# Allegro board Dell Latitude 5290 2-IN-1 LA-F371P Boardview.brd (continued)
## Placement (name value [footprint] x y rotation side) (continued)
D53  ESD8011MUT5G X3DFN2  [ESD101-B1-02ELS_TSSLP-2-4-2]  9.08 37.08 180 top
D54  ESD8011MUT5G X3DFN2  [ESD101-B1-02ELS_TSSLP-2-4-2]  8.95 29.91 0 top
D55  ESD8011MUT5G X3DFN2  [ESD101-B1-02ELS_TSSLP-2-4-2]  8.57 28.83 90 top
D56  ESD8011MUT5G X3DFN2  [ESD101-B1-02ELS_TSSLP-2-4-2]  8.57 28.2 270 top
D57  ESD8011MUT5G X3DFN2  [ESD101-B1-02ELS_TSSLP-2-4-2]  14.03 19.69 90 bottom
D58  ESD8011MUT5G X3DFN2  [ESD101-B1-02ELS_TSSLP-2-4-2]  9.21 22.99 180 top
D59  ESD8011MUT5G X3DFN2  [ESD101-B1-02ELS_TSSLP-2-4-2]  9.21 22.23 180 top
D60  -  [BAT54CW-7-F_SOT323-3]  38.35 22.1 180 top
D61  -  [BAT54CW-7-F_SOT323-3]  18.37 88.83 90 bottom
D62  -  [ESD207-B1-02EL_TSLP-2-19-2]  46.23 79.37 90 bottom
D63  -  [ESD207-B1-02EL_TSLP-2-19-2]  42.93 79.37 90 bottom
D64  -  [ESD207-B1-02EL_TSLP-2-19-2]  42.93 75.81 90 bottom
D65  -  [ESD207-B1-02EL_TSLP-2-19-2]  42.93 77.59 90 bottom
D68  ESD8011MUT5G X3DFN2  [ESD101-B1-02ELS_TSSLP-2-4-2]  18.41 37.59 270 bottom
D69  ESD8011MUT5G X3DFN2  [ESD101-B1-02ELS_TSSLP-2-4-2]  14.1 35.18 90 bottom
D70  ESD8011MUT5G X3DFN2  [ESD101-B1-02ELS_TSSLP-2-4-2]  18.41 38.23 90 bottom
D71  ESD218-B1-02ELS TSSLP-2-4  [ESD3V3S1B-02LS_PG-TSSLP-2-1-2]  9.2 39.14 0 bottom
D72  ESD8011MUT5G X3DFN2  [ESD101-B1-02ELS_TSSLP-2-4-2]  12.7 42.93 270 bottom
D73  ESD8011MUT5G X3DFN2  [ESD101-B1-02ELS_TSSLP-2-4-2]  12.7 41.53 90 bottom
D74  ESD8011MUT5G X3DFN2  [ESD101-B1-02ELS_TSSLP-2-4-2]  12.7 40.52 90 bottom
D75  ESD8011MUT5G X3DFN2  [ESD101-B1-02ELS_TSSLP-2-4-2]  12.7 39.88 270 bottom
D76  ESD8011MUT5G X3DFN2  [ESD101-B1-02ELS_TSSLP-2-4-2]  16.76 42.36 0 bottom
D77  ESD8011MUT5G X3DFN2  [ESD101-B1-02ELS_TSSLP-2-4-2]  8.06 36.64 270 bottom
D78  ESD8011MUT5G X3DFN2  [ESD101-B1-02ELS_TSSLP-2-4-2]  18.16 42.36 180 bottom
D79  ESD8011MUT5G X3DFN2  [ESD101-B1-02ELS_TSSLP-2-4-2]  14.03 18.67 90 bottom
D80  ESD8011MUT5G X3DFN2  [ESD101-B1-02ELS_TSSLP-2-4-2]  18.41 23.37 270 bottom
D81  ESD8011MUT5G X3DFN2  [ESD101-B1-02ELS_TSSLP-2-4-2]  18.41 24.01 90 bottom
D82  ESD218-B1-02ELS TSSLP-2-4  [ESD3V3S1B-02LS_PG-TSSLP-2-1-2]  9.08 24.96 0 bottom
D83  ESD8011MUT5G X3DFN2  [ESD101-B1-02ELS_TSSLP-2-4-2]  12.73 28.78 270 bottom
D84  ESD8011MUT5G X3DFN2  [ESD101-B1-02ELS_TSSLP-2-4-2]  12.73 27.38 90 bottom
D85  ESD8011MUT5G X3DFN2  [ESD101-B1-02ELS_TSSLP-2-4-2]  12.62 24.21 90 bottom
D86  ESD8011MUT5G X3DFN2  [ESD101-B1-02ELS_TSSLP-2-4-2]  12.62 23.57 270 bottom
D87  ESD8011MUT5G X3DFN2  [ESD101-B1-02ELS_TSSLP-2-4-2]  17.14 26.23 90 bottom
D88  ESD8011MUT5G X3DFN2  [ESD101-B1-02ELS_TSSLP-2-4-2]  17.14 27.67 270 bottom
D89  ESD8011MUT5G X3DFN2  [ESD101-B1-02ELS_TSSLP-2-4-2]  8.32 30.55 180 bottom
D91  RB751S40T1G_SOD523-2  [RB520SM-30T2R_EMD2-2]  22.78 93.23 180 bottom
D92  RB751S40T1G_SOD523-2  [RB520SM-30T2R_EMD2-2]  18.38 93.23 0 bottom
D94  RB751S40T1G_SOD523-2  [RB520SM-30T2R_EMD2-2]  30.98 108.69 0 top
D95  RB751S40T1G_SOD523-2  [RB520SM-30T2R_EMD2-2]  30.98 107.47 0 top
D105  RB751S40T1G_SOD523-2  [RB520SM-30T2R_EMD2-2]  21.36 104.52 180 bottom
D106  RB751S40T1G_SOD523-2  [RB520SM-30T2R_EMD2-2]  35.33 101.07 90 bottom
D107  RB751S40T1G_SOD523-2  [RB520SM-30T2R_EMD2-2]  11.66 137 0 bottom
D108  RB751S40T1G_SOD523-2  [RB520SM-30T2R_EMD2-2]  5.87 137.9 0 bottom
D109  RB751S40T1G_SOD523-2  [RB520SM-30T2R_EMD2-2]  55.92 111.25 0 bottom
D110  RB751S40T1G_SOD523-2  [RB520SM-30T2R_EMD2-2]  125.63 175.58 180 top
D111  RB751S40T1G_SOD523-2  [RB520SM-30T2R_EMD2-2]  16.61 108.22 270 bottom
D112  RB751S40T1G_SOD523-2  [RB520SM-30T2R_EMD2-2]  63.11 84.99 90 top
D113  RB751S40T1G_SOD523-2  [RB520SM-30T2R_EMD2-2]  124.02 93.55 270 top
D114  RB751S40T1G_SOD523-2  [RB520SM-30T2R_EMD2-2]  127.02 90.67 180 top
D115  -  [BAT54CW-7-F_SOT323-3]  18.54 83 90 bottom
D116  RB751S40T1G_SOD523-2  [RB520SM-30T2R_EMD2-2]  28.19 98.2 270 bottom
DA1  -  [ESD207-B1-02EL_TSLP-2-19-2]  14.55 162.24 180 bottom
DA3  -  [ESD207-B1-02EL_TSLP-2-19-2]  12.5 162.24 0 bottom
DA4  -  [ESD207-B1-02EL_TSLP-2-19-2]  9.14 162.24 0 bottom
DA5  -  [ESD207-B1-02EL_TSLP-2-19-2]  11.18 162.24 180 bottom
DA6  -  [ESD207-B1-02EL_TSLP-2-19-2]  7.82 162.24 180 bottom
DA8  -  [TVNST52302AB0_SOT523-3]  70.63 16.7 90 bottom
DA9  -  [TVNST52302AB0_SOT523-3]  70.56 13.57 90 bottom
DI1  -  [TVNST52302AB0_SOT523-3]  77.19 23.67 90 bottom
FD1  FIDUCAL  [FIDUCIAL_C40M80]  9.96 165.27 0 top
FD2  FIDUCAL  [FIDUCIAL_C40M80]  76.01 8.32 0 top
FD3  FIDUCIAL  [FIDUCIAL_C40M80]  14.59 171.05 180 bottom
FD4  FIDUCIAL  [FIDUCIAL_C40M80]  76.01 8.32 180 bottom
H1  H_2P3  [H_2P3-G]  110.5 160.15 0 top
H2  H_2P3  [H_2P3-G]  159.4 163.15 0 top
H3  H_2P3  [H_2P3-G]  159.9 109.8 0 top
H4  H_2P3  [H_2P3-G]  118.5 88.8 0 top
H5  -  [H_3P3]  46.2 113.26 0 top
H6  H_2P3  [H_2P3-G]  11.2 90.75 0 top
H7  H_4P0  [H_4P0-G]  5.9 49.3 0 top
H8  H_4P0  [H_4P0-G]  5.9 17.6 0 top
H9  H_2P3  [H_2P3-G]  7.3 177 0 top
H10  -  [H_3P3]  45.79 133.37 0 top
H11  -  [H_3P3]  103.33 134.56 0 top
H12  H_3P6  [H_3P6-G]  82 12.05 0 top
H13  -  [H_3P3]  102.33 110.56 0 top
H14  -  [H_6P0N]  23.63 160.15 0 top
H15  -  [H_6P0N]  28.72 86.5 0 top
H16  -  [H_1P5N]  3.45 146 0 top
H17  -  [H_1P5N]  159.4 159.4 0 top
JANT1  EMI_SPRING  [CLIP_2P8X2P5-S]  67.66 169.6 0 top
JANT2  EMI_SPRING  [CLIP_2P8X2P5-S]  52.15 169.6 0 top
JANT3  BELLW_10093-1021  [BELLW_10093-1021_4P]  38 166.08 90 top
JANT7  EMI_SPRING  [CLIP_2P8X2P5-S]  103.98 169.6 0 top
JAPS1  ACES_50506-01841-P01  [ACES_50506-01841-P01_18P]  28.64 160.85 0 bottom
JCR1  T-SOL_158-1000902614  [T-SOL_158-1000902614_23P-T]  70.14 80.4 180 bottom
JDEG3  ACES_50521-01041-P01  [ACES_50521-01041-P01_10P]  39.21 90.95 180 top
JEDP1  ACES_50398-05071-001  [ACES_50398-05071-001_50P-T]  85.1 20.7 90 top
JESPI1  ACES_50521-01041-P01  [ACES_50521-01041-P01_10P]  55.05 97.31 270 top
JFAN1  ACES_50224-00401-001  [ACES_50224-00401-001_4P]  155.52 134.56 90 top
JIO1  JAE_WP7B-S040VA1-R6000  [JAE_WP7B-S040VA1-R6000_40P-T]  138.05 89.95 180 top
JIO2  ACES_51522-03001-P01  [ACES_51522-03001-P01_30P]  74.55 53.15 90 top
JIR1  ACES_50208-01201-P01  [ACES_50208-01201-P01_12P]  15.1 93.35 90 top
JNGFF1  LOTES_APCI0144-P007A  [LOTES_APCI0144-P007A_75P]  32.88 114.62 180 top
JNGFF2  LOTES_APCI0146-P004A  [LOTES_APCI0146-P004A_75P]  46 82.79 0 top
JNGFF3  LOTES_APCI0145-P004A  [LOTES_APCI0145-P004A_75P]  37.97 52.98 180 top
JP1  SINGA_2SJ3157-001111F  [SINGA_2SJ3157-001111F_6P-T]  6.66 168.55 90 top
JRTC1  ACES_50278-00201-001  [ACES_50278-00201-001_2P]  154.74 99.4 225 bottom
JSIM1  JAE_SF56S006V4A  [JAE_SF56S006V4A_6P-T]  52.04 69.06 180 bottom
JSPI2  ACES_50521-01041-P01  [ACES_50521-01041-P01_10P]  48.65 92.81 90 bottom
JSPK  ACES_50376-00601-001  [ACES_50376-00601-001_6P-T]  81.35 4.8 0 top
JT100  ACES_50278-01201-001  [ACES_50278-01201-001_12P-T]  145.33 89.34 90 top
JUART  CVILU_CI1804M1VRA-NH  [CVILU_CI1804M1VRA-NH_4P]  46.15 123.83 270 bottom
JUFC1  HRS_DF37NC-30DS-0P4V(51)  [HRS_DF37NC-30DS-0P4V-51_30P-T]  121.58 167.59 90 top
JUSB1  TAIWI_USB036-10B7CRL-TW  [TAIWI_USB036-10B7CRL-TW_10P-T]  8.81 106.37 270 top
JUSBC1  JAE_DX07S024XJ2  [JAE_DX07S024XJ2_24P-T]  7.11 43.5 270 top
JUSBC2  JAE_DX07S024XJ2  [JAE_DX07S024XJ2_24P-T]  7.11 28.9 270 top
JWFC1  JAE_WP7B-S034VA1  [JAE_WP7B-S034VA1_34P-T]  121.71 156.94 90 top
JXDP1  JXT_FP270H-061G1AM  [JXT_FP270H-061G1AM_61P]  153.21 118.3 90 bottom
L9  DLW21HN900HQ2L_4P  [MURAT_DLW21HN900HQ2L_4P]  20.3 110.58 90 top
L10  DLW21HN900HQ2L_4P  [MURAT_DLW21HN900HQ2L_4P]  31.67 110.21 90 top
L12  BLM15PX330SN1D_2P  [MURAT_BLM15PX330SN1D_2P]  14.22 159.71 90 bottom
L13  22NH_LQG15HS22NJ02D_5%  [MURAT_LQG15HS22NJ02D_2P]  108.89 169.15 90 top
L14  22NH_LQG15HS22NJ02D_5%  [MURAT_LQG15HS22NJ02D_2P]  109.91 169.15 90 top
L15  BLM15PX330SN1D_2P  [MURAT_BLM15PX330SN1D_2P]  12.83 159.71 90 bottom
L16  BLM15AG121SN1D_L0402_2P  [MURAT_BLM15AG121SN1D_L0402_2P]  111.23 167.07 0 top
L17  BLM15AG121SN1D_L0402_2P  [MURAT_BLM15AG121SN1D_L0402_2P]  111.23 168.21 0 top
L18  BLM15AX700SN1D_2P  [MURAT_BLM15AX100SN1D_2P]  9.27 159.83 180 bottom
L19  BLM15AX700SN1D_2P  [MURAT_BLM15AX100SN1D_2P]  10.8 159.83 0 bottom
L20  BLM15HD601SN1D_2P  [MURAT_BLM15HD182SN1D_2P]  151.64 148.9 270 bottom
L21  BLM15HD601SN1D_2P  [MURAT_BLM15HD182SN1D_2P]  150.37 148.9 270 bottom
L22  1UH_1269AS-H-1R0M-P2_2.5A_20%  [TOKO_1269AS-H-1R0M-P2_2P]  147.19 140.77 270 bottom
L23  BLM18EG221SN1D_2P  [MURAT_BLM18EG221SN1D_2P]  59.22 122.24 0 bottom
L24  HCM1012GH900BP_4P  [INPAQ_HCM1012GH900BP_4P]  25.79 54.35 270 bottom
L30  BLM18EG221SN1D_2P  [MURAT_BLM18EG221SN1D_2P]  59.31 123.42 90 bottom
L31  BLM18SG221TN1D_2P  [MURAT_BLM18SG221TN1D_2P]  22.53 89.38 0 bottom
L32  BLM18SG221TN1D_2P  [MURAT_BLM18SG221TN1D_2P]  22.53 87.94 0 bottom
L80  1.8NH +-0.1NH LQP03TN1N8B02D  [MURAT_LQP03TN1N8B00D_2P]  108.78 165.33 90 top
L81  1.8NH +-0.1NH LQP03TN1N8B02D  [MURAT_LQP03TN1N8B00D_2P]  42.9 166.5 0 top
LA1  BLM21PG600SN1D_2P  [MURAT_BLM21PG600SN1D_2P]  35.43 147.94 270 bottom
LA2  0_0603_5%  [R_0603]  32.32 146.81 90 bottom
LA3  0_0603_5%  [R_0603]  33.53 146.94 270 bottom
LA5  BLM15PX181SN1D_2P  [MURAT_BLM15PX181SN1D_2P]  67.32 17.34 0 bottom
LA6  BLM15PX181SN1D_2P  [MURAT_BLM15PX181SN1D_2P]  67.32 16.26 0 bottom
LA7  BLM15PX181SN1D_2P  [MURAT_BLM15PX181SN1D_2P]  66.43 13.59 0 bottom
LA8  BLM15PX181SN1D_2P  [MURAT_BLM15PX181SN1D_2P]  66.43 12.45 0 bottom
LED4  HT-191UD5_AMBER  [LED_HT-191UD5_2P]  52.31 87.43 270 top
LED5  HT-191UD5_AMBER  [LED_HT-191UD5_2P]  49.05 84.67 180 top
LGA1  -  [LSM6DS3USTR_LGA14_2P5X3]  8.97 143.65 270 bottom
LS1  10NH_LQG15HS10NJ02D_5%_0402  [MURAT_LQG15HS10NJ02D_2P]  116.32 161.58 270 bottom
LT1  HCB2012KF-121T50_2P  [TAI-T_HCB2012KF-121T50_2P]  4.31 33.85 0 top
LT2  HCB2012KF-121T50_2P  [TAI-T_HCB2012KF-121T50_2P]  8.83 32.86 90 top
MC1  680P_0402_50V7K  [C_0402]  79.49 83.61 0 top
MD1  AZ1065-06Q.RDG_MSOP8  [AZ1065-06QPRDG_MSOP8]  21.12 99.65 0 bottom
MIC1  SPK0641HT4H-1-7_8P  [CIRRU_WM7216IMSE-RV_5P]  19.13 173.88 90 top
MIC2  SPK0641HT4H-1-7_8P  [CIRRU_WM7216IMSE-RV_5P]  111.68 174.78 90 top
MIC3  SPK0641HT4H-1-7_8P  [CIRRU_WM7216IMSE-RV_5P]  3.68 125.99 180 top
ML1  CMMI21T-670Y-N_4P  [MURAT_DLW21SN670HQ2L_4P]  24.15 110.59 90 top
ML2  CMMI21T-670Y-N_4P  [MURAT_DLW21SN670HQ2L_4P]  26.18 110.59 90 top
ML3  DLW21HN900HQ2L_4P  [MURAT_DLW21HN900HQ2L_4P]  29.68 104.19 180 top
ML4  CMMI21T-670Y-N_4P  [MURAT_DLW21SN670HQ2L_4P]  21.36 103.02 270 bottom
ML5  CMMI21T-670Y-N_4P  [MURAT_DLW21SN670HQ2L_4P]  23.26 103.02 270 bottom
ML6  DLW21HN900HQ2L_4P  [MURAT_DLW21HN900HQ2L_4P]  25.19 98.96 270 bottom
ML7  HCM1012GH900BP_4P  [INPAQ_HCM1012GH900BP_4P]  33.16 69.3 0 bottom
ML8  HCM1012GH900BP_4P  [INPAQ_HCM1012GH900BP_4P]  36.97 54.28 270 bottom
ML9  MCM1012B900F06BP_4P  [INPAQ_MCM1012B900F06BP_4P]  14.98 42.48 180 bottom
ML10  MCM1012B900F06BP_4P  [INPAQ_MCM1012B900F06BP_4P]  14.98 40.45 180 bottom
ML11  MCM1012B900F06BP_4P  [INPAQ_MCM1012B900F06BP_4P]  15 28.33 180 bottom
ML12  MCM1012B900F06BP_4P  [INPAQ_MCM1012B900F06BP_4P]  15.41 24.14 180 bottom
ML14  HCM1012GH900BP_4P  [INPAQ_HCM1012GH900BP_4P]  50.17 17.34 0 bottom
NOREF  -  []  50.8 39.16 0 top
NOREF#2  -  []  50.77 52.53 0 top
NOREF#3  -  []  52.29 17.34 0 top
NOREF#4  -  []  103.33 134.56 0 top
NOREF#5  -  []  46.2 113.26 0 top
NOREF#6  -  []  48.82 38.62 0 top
NOREF#7  -  []  110.5 160.15 0 top
NOREF#8  -  []  61.35 27.6 0 top
NOREF#9  -  []  82 12.05 0 top
NOREF#10  -  []  109.31 32.44 0 top
NOREF#11  -  []  159.9 109.8 0 top
NOREF#12  -  []  110.5 160.15 0 top
NOREF#13  -  []  118.5 88.8 0 top
NOREF#14  -  []  97.41 74.74 0 top
NOREF#15  -  []  28.83 72.71 0 top
NOREF#16  -  []  11.2 90.75 0 top
NOREF#17  -  []  69.43 33.46 0 top
NOREF#18  -  []  0 178.5 0 top
NOREF#19  -  []  75.2 22.38 270 top
NOREF#20  -  []  7.3 177 0 top
NOREF#21  -  []  159.4 163.15 0 top
NOREF#22  -  []  102.33 110.56 0 top
NOREF#23  -  []  43.05 64.66 0 top
NOREF#24  -  []  45.79 133.37 0 top
NOREF#25  -  []  76.21 50.34 180 bottom
NOREF#26  -  []  84.78 45.38 180 bottom
PC100  2200P_0402_50V7K  [C_0402]  13.63 41.86 90 top
PC101  0.1U_0402_25V6  [C_0402]  12.69 41.86 90 top
PC102  100P_0201_25V7K  [C_0201]  13.49 38.04 270 top
PC103  0.01U_0402_25V7K  [C_0402]  12.75 37.96 270 top
PC104  1000P_0201_50V7K  [C_0201]  19.91 40.74 90 top
PC105  100P_0201_25V7K  [C_0201]  19.25 40.74 90 top
PC106  0.1U_0402_25V6  [C_0402]  14.63 41.85 90 top
PC107  1U_0603_25V6K  [C_0603]  18.06 40.88 90 top
PC108  2200P_0402_50V7K  [C_0402]  15.6 41.85 90 top
PC109  0.47U_0402_25V6K  [C_0402]  15.42 37.96 270 top
PC110  680P_0402_50V7K  [C_0402]  36.7 32.45 90 top
PC111  680P_0402_50V7K  [C_0402]  27.79 36.72 90 top
PC112  680P_0402_50V7K  [C_0402]  29.72 33.72 180 top
PC114  100P_0201_25V7K  [C_0201]  12.67 25.67 270 top
PC115  1U_0603_25V6K  [C_0603]  16.48 29.35 90 top
PC116  0.1U_0402_25V6  [C_0402]  13.28 30.29 0 top
PC117  2200P_0402_50V7K  [C_0402]  17.55 28.27 90 top
PC118  100P_0201_25V7K  [C_0201]  21.01 28.3 90 top
PC119  1000P_0201_50V7K  [C_0201]  20.38 28.3 90 top
PC120  2200P_0402_50V7K  [C_0402]  13.28 29.4 0 top
PC121  0.1U_0402_25V6  [C_0402]  18.54 28.26 90 top
PC122  0.01U_0402_25V7K  [C_0402]  13.46 25.59 270 top
PC123  0.47U_0402_25V6K  [C_0402]  14.35 25.59 270 top
PC124  680P_0402_50V7K  [C_0402]  24.51 24.4 270 top
PC125  0.01U_0201_16V7  [C_0201]  23.27 43.97 90 top
PC126  1000P_0402_50V7K  [C_0402]  140.21 106.95 270 top
PC127  0.01U_0402_25V7K  [C_0402]  139.83 111.11 90 bottom
PC128  1U_0603_25V6K  [C_0603]  14.61 48.58 180 top
PC129  1U_0402_16V6K  [C_0402]  22.06 48.78 270 top
PC130  0.1U_0201_10V6K  [C_0201]  27.3 43.41 270 top
PC131  1U_0402_16V6K  [C_0402]  20.19 48.68 0 bottom
PC132  2200P_0402_50V7K  [C_0402]  139.06 106.03 90 top
PC133  10U_0603_25V6M  [C_0603]  16.78 40.88 90 top
PC134  10U_0603_25V6M  [C_0603]  15.21 29.35 90 top
PC140  1000P_0402_50V7K  [C_0402]  143.03 127.46 180 top
PC144  100P_0402_50V8J  [C_0402]  28.57 48.83 90 bottom
PC145  0.1U_0402_10V7K  [C_0402]  30.73 49.34 90 bottom
PC146  2.2U_0402_25V6M  [C_0402]  31.88 47.36 90 bottom
PC147  0.1U_0402_10V7K  [C_0402]  39.57 47.68 180 top
PC148  100P_0402_50V8J  [C_0402]  37.22 38.93 180 top
PC149  2.2U_0402_25V6M  [C_0402]  39.55 44.79 90 top
PC150  0.01U_0402_50V7K  [C_0402]  30.3 48.07 270 top
PC151  0.01U_0402_50V7K  [C_0402]  35.45 40.71 180 top
PC280  4.7U_0402_6.3V6M  [C_0402]  144.78 118.7 270 top
PC281  10U_0402_6.3V6M  [C_0402]  30.1 46.24 270 bottom
PC282  10U_0402_6.3V6M  [C_0402]  38.02 43.94 0 top
PC283  0.1U_0402_10V7K  [C_0402]  31.88 22.16 0 top
PC284  100P_0402_50V8J  [C_0402]  35.81 21.27 0 top
PC285  10U_0402_6.3V6M  [C_0402]  35.81 18.99 270 top
PC286  0.01U_0402_50V7K  [C_0402]  30.73 18.48 270 top
PC301  0.1U_0402_25V6  [C_0402]  120.64 97.92 0 top
PC302  10U_0603_25V6M  [C_0603]  128.91 98.74 0 top
PC303  0.1U_0402_25V6  [C_0402]  127.76 98.62 270 top
PC304  10U_0603_25V6M  [C_0603]  129.54 98.93 270 bottom
PC305  10U_0603_25V6M  [C_0603]  124.46 101.35 90 bottom
PC306  2200P_0402_50V7K  [C_0402]  127.13 98.82 270 bottom
PC307  10U_0603_25V6M  [C_0603]  124.59 97.86 180 top
PC308  10U_0603_25V6M  [C_0603]  123.19 101.35 90 top
PC309  10U_0603_25V6M  [C_0603]  124.46 101.35 90 top
PC310  10U_0603_25V6M  [C_0603]  128.27 98.93 270 bottom
PC312  4.7U_0603_25V6K  [C_0603]  131.19 128.4 270 bottom
PC313  1U_0402_25V6K  [C_0402]  132.77 127.83 0 top
PC314  1U_0402_25V6K  [C_0402]  132.77 126.94 0 top
PC315  10U_0603_25V6M  [C_0603]  143 121.54 90 bottom
PC316  10U_0603_25V6M  [C_0603]  144.27 121.54 90 top
PC317  10U_0603_25V6M  [C_0603]  143 121.54 90 top
PC318  10U_0603_25V6M  [C_0603]  140.46 121.54 90 top
PC319  10U_0603_25V6M  [C_0603]  140.46 121.54 90 bottom
PC320  10U_0603_25V6M  [C_0603]  139.19 121.54 90 top
PC321  0.1U_0402_25V6  [C_0402]  145.41 121.78 90 top
PC322  10U_0603_25V6M  [C_0603]  143.07 116.71 0 bottom
PC323  10U_0603_25V6M  [C_0603]  143.07 116.71 0 top
PC324  10U_0603_25V6M  [C_0603]  144.27 121.54 90 bottom
PC325  10U_0603_25V6M  [C_0603]  141.73 121.54 90 top
PC326  10U_0603_25V6M  [C_0603]  141.73 121.54 90 bottom
PC327  1U_0402_25V6K  [C_0402]  80.58 158.87 90 top
PC328  1U_0402_25V6K  [C_0402]  63.69 158.93 90 top
PC329  2200P_0402_50V7K  [C_0402]  145.41 121.78 90 bottom
PC330  0.22U_0603_25V7K  [C_0603]  129.73 124.65 0 bottom
PC331  0.1U_0402_25V6  [C_0402]  134.71 130.81 90 bottom
PC332  1U_0603_25V6K  [C_0603]  130.75 129.48 180 bottom
PC333  1U_0603_25V6K  [C_0603]  131.83 132.34 270 bottom
PC334  1U_0402_6.3V6K  [C_0402]  132.77 128.72 0 top
PC335  1U_0402_6.3V6K  [C_0402]  134.54 128.46 0 top
PC336  0.22U_0603_25V7K  [C_0603]  135 122.56 270 bottom
PC337  1U_0402_25V6K  [C_0402]  93.28 156.14 90 top
PC338  1U_0402_25V6K  [C_0402]  53.85 155.37 90 top
PC339  4700P_0402_25V7K  [C_0402]  138.63 117.54 180 top
PC340  2200P_0402_50V7K  [C_0402]  137.41 114.61 90 top
PC341  0.1U_0402_25V6  [C_0402]  135.13 123.94 90 top
PC342  680P_0402_50V7K  [C_0402]  134.37 100.47 270 bottom
PC343  680P_0402_50V7K  [C_0402]  127.51 120.64 90 bottom
PC345  1U_0402_25V6K  [C_0402]  136.21 120.89 90 bottom
PC346  4.7U_0603_25V6K  [C_0603]  136.84 122.87 0 bottom
PC347  1U_0402_25V6K  [C_0402]  138.87 121.81 270 bottom
PC348  560P_0402_50V7K  [C_0402]  139.24 127.7 0 bottom
PC349  0.01U_0402_16V7K  [C_0402]  140.14 125.85 90 bottom
PC350  0.1U_0402_25V6  [C_0402]  32.01 121.56 270 bottom
PC351  0.1U_0402_25V6  [C_0402]  139.24 125.41 0 top
PC352  0.1U_0402_25V6  [C_0402]  154.72 125.49 90 top
PC400  0.1U_0603_50V7K  [C_0603]  77.85 73.79 270 top
PC401  1U_0805_50V7K  [C_0805]  77.85 74.91 90 top
PC402  0.1U_0402_25V6  [C_0402]  77.71 81.83 0 top
PC403  2.2U_0603_50V6K  [C_0603]  70.68 67.25 180 top
PC404  2.2U_0603_50V6K  [C_0603]  70.68 68.52 180 top
PC405  2.2U_0603_50V6K  [C_0603]  71.69 71.06 0 top
PC406  0.1U_0603_50V7K  [C_0603]  71.69 69.79 0 top
PC407  220P_0402_50V7K  [C_0402]  69.28 76 90 top
PC408  470P_0402_50V7K  [C_0402]  76.71 85.92 180 top
PC409  470P_0402_50V7K  [C_0402]  76.71 84.06 90 top
PC410  470P_0402_50V7K  [C_0402]  75.82 84.06 90 top
PC411  100P_0402_50V8J  [C_0402]  69.39 86.17 0 top
PC412  470P_0402_50V7K  [C_0402]  74.93 84.06 90 top
PC413  470P_0402_50V7K  [C_0402]  74.04 84.06 90 top
PC414  470P_0402_50V7K  [C_0402]  73.15 84.06 90 top
PC415  470P_0402_50V7K  [C_0402]  72.21 84.14 180 top
PC416  100P_0402_50V8J  [C_0402]  79.45 78.82 270 top
PC417  470P_0402_50V7K  [C_0402]  70.31 82.62 180 top
PC418  2.2U_0603_50V6K  [C_0603]  71.64 68.52 0 top
PC500  0.22U_0402_16V7K  [C_0402]  123.27 114.11 180 top
PC501  0.1U_0402_25V6  [C_0402]  119.84 120.33 180 top
PC502  2200P_0402_50V7K  [C_0402]  119.84 120.33 180 bottom
PC503  10U_0603_25V6M  [C_0603]  120.08 121.48 180 bottom
PC504  10U_0603_25V6M  [C_0603]  120.08 121.48 180 top
PC505  4.7U_0402_6.3V6M  [C_0402]  116.4 118.25 270 top
PC506  22U_0603_6.3V6M  [C_0603]  118.05 107 180 top
PC507  22U_0603_6.3V6M  [C_0603]  118.05 107 180 bottom
PC508  22U_0603_6.3V6M  [C_0603]  120.33 107 0 bottom
PC509  22U_0603_6.3V6M  [C_0603]  120.33 107 0 top
PC510  1U_0402_16V6K  [C_0402]  122.43 116.26 90 top
PC511  680P_0603_50V7K  [C_0603]  119.7 117.79 180 bottom
PC513  0.22U_0402_16V7K  [C_0402]  41.71 156.53 0 top
PC514  0.47U_0402_25V6K  [C_0402]  45.26 152.59 0 bottom
PC515  0.047U_0402_25V7K  [C_0402]  45.26 153.48 0 bottom
PC516  10U_0603_25V6M  [C_0603]  45.59 151.47 0 top
PC517  10U_0603_25V6M  [C_0603]  45.59 151.32 0 bottom
PC518  4.7U_0402_6.3V6M  [C_0402]  48.9 156.1 270 top
PC519  22U_0603_6.3V6M  [C_0603]  48.45 162.37 0 top
PC520  22U_0603_6.3V6M  [C_0603]  48.45 161.1 0 bottom
PC521  22U_0603_6.3V6M  [C_0603]  48.45 162.37 0 bottom
PC522  22U_0603_6.3V6M  [C_0603]  48.45 161.1 0 top
PC523  1U_0402_16V6K  [C_0402]  42.67 154.32 270 top
PC524  680P_0603_50V7K  [C_0603]  48.32 156.15 0 bottom
PC526  0.22U_0402_16V7K  [C_0402]  123.52 140.45 180 top
PC527  0.1U_0402_25V6  [C_0402]  120.35 147.18 180 top
PC528  2200P_0402_50V7K  [C_0402]  120.35 147.18 180 bottom
PC529  10U_0603_25V6M  [C_0603]  120.33 148.32 180 bottom
PC530  10U_0603_25V6M  [C_0603]  120.33 148.32 180 top
PC531  4.7U_0402_6.3V6M  [C_0402]  116.59 143.04 90 top
PC532  22U_0603_6.3V6M  [C_0603]  116.59 144.9 90 top
PC533  22U_0603_6.3V6M  [C_0603]  122.62 138.29 0 bottom
PC534  22U_0603_6.3V6M  [C_0603]  122.62 137.02 0 bottom
PC535  22U_0603_6.3V6M  [C_0603]  122.62 137.02 0 top
PC536  1U_0402_16V6K  [C_0402]  123 142.66 90 top
PC537  680P_0603_50V7K  [C_0603]  118.36 144.45 90 bottom
PC600  0.22U_0402_16V7K  [C_0402]  112.09 116.02 180 top
PC601  680P_0402_50V7K  [C_0402]  105.87 120.46 180 bottom
PC602  220P_0402_50V8J  [C_0402]  111.84 118.3 180 top
PC603  22U_0603_6.3V6M  [C_0603]  108.78 106.24 180 top
PC604  22U_0603_6.3V6M  [C_0603]  108.78 107.51 180 top
PC605  22U_0603_6.3V6M  [C_0603]  110.17 106.24 0 top
PC606  22U_0603_6.3V6M  [C_0603]  110.17 107.51 0 top
PC607  10U_0603_25V6M  [C_0603]  107.77 124.54 180 top
PC608  0.1U_0402_25V6  [C_0402]  108 123.18 180 top
PC609  2200P_0402_25V7K  [C_0402]  108 122.3 180 top
PC610  10U_0402_6.3V6M  [C_0402]  104.47 119.45 180 top
PC611  10U_0402_6.3V6M  [C_0402]  104.47 118.49 180 top
PC612  0.22U_0402_10V6K  [C_0402]  104.47 119.45 180 bottom
PC613  0.1U_0402_10V7K  [C_0402]  107.31 122.42 90 bottom
PC614  1U_0402_16V6K  [C_0402]  104.47 120.72 180 top
PC615  0.1U_0402_10V7K  [C_0402]  110.92 121.86 0 top
PC700  0.22U_0402_10V6K  [C_0402]  131.95 138.57 270 top
PC701  680P_0402_50V7K  [C_0402]  128.91 144.54 270 bottom
PC702  0.1U_0603_25V7K  [C_0603]  124.9 144.65 0 top
PC703  2200P_0402_50V7K  [C_0402]  125.74 141.23 180 top
PC704  0.1U_0402_25V6  [C_0402]  125.68 141.23 180 bottom
PC705  10U_0603_25V6M  [C_0603]  125.35 140.07 270 bottom
PC706  10U_0603_25V6M  [C_0603]  125.35 140.07 270 top
PC707  330P_0402_50V7K  [C_0402]  132.79 140.84 180 bottom
PC708  22U_0603_6.3V6M  [C_0603]  131.76 146.5 0 top
PC709  22U_0603_6.3V6M  [C_0603]  131.76 146.5 0 bottom
PC710  22U_0603_6.3V6M  [C_0603]  131.76 147.77 0 bottom
PC711  22U_0603_6.3V6M  [C_0603]  131.76 147.77 0 top
PC712  2.2U_0402_6.3V6M  [C_0402]  131.81 143.38 0 top
PC713  4.7U_0603_6.3V6K  [C_0603]  131.76 142.31 0 top
PC720  0.1U_0402_25V6  [C_0402]  142.82 140.91 180 top
PC721  22P_0402_50V8J  [C_0402]  135.05 143.32 0 top
PC722  22U_0603_6.3V6M  [C_0603]  135.95 144.97 180 top
PC723  0.1U_0402_25V6  [C_0402]  140.11 138.42 270 top
PC724  2200P_0402_50V7K  [C_0402]  139.22 138.42 270 top
PC725  10U_0603_25V6M  [C_0603]  141.15 138.41 270 top
PC726  3300P_0402_50V7-K  [C_0402]  138.33 138.43 270 top
PC727  680P_0402_50V7K  [C_0402]  137.6 143.14 270 bottom
PC728  0.1U_0402_25V6  [C_0402]  104.44 96.59 0 top
PC729  22P_0402_50V8J  [C_0402]  112.2 95.45 270 top
PC730  22U_0603_6.3V6M  [C_0603]  108.53 89.9 270 top
PC731  0.1U_0402_25V6  [C_0402]  107.57 99.43 90 top
PC732  2200P_0402_50V7K  [C_0402]  108.46 99.43 90 top
PC733  10U_0603_25V6M  [C_0603]  109.6 99.44 90 top
PC734  3300P_0402_50V7-K  [C_0402]  111.3 98.11 0 top
PC735  680P_0402_50V7K  [C_0402]  105.54 92.32 90 top
PC736  22U_0603_6.3V6M  [C_0603]  109.82 89.9 270 top
PC800  0.1U_0402_25V6  [C_0402]  124.08 130.8 90 top
PC801  10U_0603_25V6M  [C_0603]  126.81 128.21 0 top
PC802  10U_0603_25V6M  [C_0603]  126.81 128.21 0 bottom
PC803  22U_0603_6.3V6M  [C_0603]  119.44 129.8 0 top
PC804  22U_0603_6.3V6M  [C_0603]  119.44 132.4 0 top
PC805  22U_0603_6.3V6M  [C_0603]  119.43 131.09 0 top
PC806  0.1U_0402_25V6  [C_0402]  126.8 127.07 0 top
PC807  2200P_0402_50V7K  [C_0402]  126.8 127.07 0 bottom
PC808  680P_0402_50V7K  [C_0402]  122.36 127.24 90 bottom
PC809  100P_0402_50V8J  [C_0402]  123.83 124.6 270 top
PC810  0.1U_0402_25V6  [C_0402]  50.28 147.77 0 top
PC811  10U_0603_25V6M  [C_0603]  52.64 146.5 0 top
PC812  10U_0603_25V6M  [C_0603]  52.64 146.5 0 bottom
PC813  22U_0603_6.3V6M  [C_0603]  45.97 147.13 90 bottom
PC814  22U_0603_6.3V6M  [C_0603]  45.97 147.13 90 top
PC815  22U_0603_6.3V6M  [C_0603]  44.77 147.13 90 top
PC816  0.1U_0402_25V6  [C_0402]  52.63 145.35 0 bottom
PC817  2200P_0402_50V7K  [C_0402]  52.63 145.35 0 top
PC818  680P_0402_50V7K  [C_0402]  49.28 147.08 270 bottom
PC819  470P_0402_50V7K  [C_0402]  50.16 141.75 270 top
PC900  0.1U_0402_25V6  [C_0402]  54.76 150.97 0 bottom
PC901  1U_0603_10V6K  [C_0603]  63.09 149.65 0 bottom
PC902  4.7U_0603_10V6K  [C_0603]  55.88 153.9 180 bottom
PC903  0.1U_0402_25V6  [C_0402]  63.42 145.16 270 bottom
PC904  220P_0402_50V8J  [C_0402]  68.1 155.79 180 bottom
PC905  470P_0402_50V7K  [C_0402]  66.32 153.76 180 bottom
PC906  33P_0402_50V8J  [C_0402]  66.32 152.87 180 bottom
PC907  1U_0603_10V6K  [C_0603]  55.04 155.96 180 bottom
PC911  0.01U_0402_50V7K  [C_0402]  55.95 159.39 270 bottom
PC931  0.01U_0402_16V7K  [C_0402]  58.55 160.24 180 bottom
PC932  0.01U_0402_16V7K  [C_0402]  66.42 159.83 0 bottom
PC933  0.01U_0402_16V7K  [C_0402]  68.98 155.87 270 bottom
PC1003  47U_D3_20VM_R45M  [C_PSKV151D476M045C]  76.66 161.05 270 top
PC1007  1000P_0402_50V7K  [C_0402]  82 162.99 90 top
PC1008  1000P_0402_50V7K  [C_0402]  97.94 159.78 0 top
PC1009  1U_0603_25V6K  [C_0603]  82.42 156.85 180 top
PC1010  10U_0603_25V6M  [C_0603]  66.61 162.63 0 top
PC1011  1000P_0402_50V7K  [C_0402]  65.15 163.01 90 top
PC1012  1000P_0402_50V7K  [C_0402]  53.85 158.64 270 top
PC1013  1U_0603_25V6K  [C_0603]  94.77 154.23 270 top
PC1014  1U_0603_25V6K  [C_0603]  55.66 153.35 180 top
PC1028  47U_D3_20VM_R45M  [C_PSKV151D476M045C]  94.64 161.79 180 top
PC1030  47U_D3_20VM_R45M  [C_PSKV151D476M045C]  57.96 161.46 180 top
PC1103  100P_0603_50V7  [C_0603]  83.31 161.42 0 bottom
PC1104  10U_0603_25V6M  [C_0603]  83.31 162.63 0 bottom
PC1105  10U_0603_25V6M  [C_0603]  83.31 162.63 0 top
PC1106  0.1U_0402_25V6  [C_0402]  81.1 162.98 90 top
PC1107  100P_0603_50V7  [C_0603]  69.15 161.37 90 bottom
PC1108  680P_0603_50V7K  [C_0603]  91.3 158.84 180 top
PC1109  10U_0603_25V6M  [C_0603]  66.61 162.63 0 bottom
PC1110  0.22U_0603_25V7K  [C_0603]  79.88 157.93 270 top
PC1111  680P_0603_50V7K  [C_0603]  71.17 159.72 270 top
PC1112  0.1U_0402_25V6  [C_0402]  64.27 163.01 90 top
PC1113  1U_0603_25V6K  [C_0603]  65.53 156.85 180 top
PC1114  0.22U_0603_25V7K  [C_0603]  63.04 157.79 270 top
PC1115  100P_0603_50V7  [C_0603]  97.57 157.61 0 bottom
PC1116  10U_0603_25V6M  [C_0603]  97.57 158.82 0 bottom
PC1117  680P_0603_50V7K  [C_0603]  102.93 157.18 180 top
PC1118  0.1U_0402_25V6  [C_0402]  98.02 161.89 0 top
PC1119  10U_0603_25V6M  [C_0603]  97.98 160.82 0 top
PC1120  0.22U_0603_25V7K  [C_0603]  93.09 155.04 270 top
PC1121  10U_0603_25V6M  [C_0603]  59.44 158.62 270 top
PC1122  10U_0603_25V6M  [C_0603]  60.64 158.62 270 top
PC1123  0.1U_0402_25V6  [C_0402]  52.96 158.64 270 top
PC1124  680P_0603_50V7K  [C_0603]  54.76 149.37 270 top
PC1125  43P_0603_50V8  [C_0603]  51.88 158.56 270 top
PC1126  0.22U_0603_25V7K  [C_0603]  53.1 154.47 270 top
PC1200  220U_B2_2.5VM_R15M  [C_B2]  75.64 145.96 270 top
PC1201  220U_B2_2.5VM_R15M  [C_B2]  91.23 142.46 180 top
PC1202  220U_B2_2.5VM_R15M  [C_B2]  78.84 145.96 270 top
PC1203  220U_B2_2.5VM_R15M  [C_B2]  92.51 145.65 270 top
PC1207  220U_B2_2.5VM_R15M  [C_B2]  100.97 142.48 0 top
PC1208  220U_B2_2.5VM_R15M  [C_B2]  108.91 141.75 180 top
PC1209  220U_B2_2.5VM_R15M  [C_B2]  108.91 145.11 180 top
PC1210  10U_0402_6.3V6M  [C_0402]  92.08 123.18 90 bottom
PC1211  10U_0402_6.3V6M  [C_0402]  92.96 123.18 90 bottom
PC1212  10U_0402_6.3V6M  [C_0402]  89.98 126.51 270 bottom
PC1213  10U_0402_6.3V6M  [C_0402]  89.03 129.86 90 bottom
PC1214  10U_0402_6.3V6M  [C_0402]  84.66 132.53 180 bottom
PC1215  10U_0402_6.3V6M  [C_0402]  84.66 131.64 180 bottom
PC1216  10U_0402_6.3V6M  [C_0402]  84.66 130.75 180 bottom
PC1217  220U_B2_2.5VM_R15M  [C_B2]  57.76 142.18 0 top
PC1218  10U_0402_6.3V6M  [C_0402]  91.69 128.77 90 bottom
PC1220  47U_0603_6.3V6M  [C_0603]  73.47 127.45 0 bottom
PC1221  10U_0402_6.3V6M  [C_0402]  73.55 131.7 180 bottom
PC1222  47U_0603_6.3V6M  [C_0603]  73.47 126.24 0 bottom
PC1223  47U_0805_6.3V6M  [C_0805]  78.21 137.67 0 bottom
PC1224  47U_0805_6.3V6M  [C_0805]  78.21 135.96 0 bottom
PC1225  10U_0402_6.3V6M  [C_0402]  78.16 131.7 0 bottom
PC1227  47U_0805_6.3V6M  [C_0805]  78.21 134.24 0 bottom
PC1228  47U_0805_6.3V6M  [C_0805]  74.51 137.67 180 bottom
PC1229  10U_0402_6.3V6M  [C_0402]  72.91 129.03 180 bottom
PC1230  47U_0805_6.3V6M  [C_0805]  77.62 124.78 180 bottom
PC1231  47U_0805_6.3V6M  [C_0805]  73.06 124.78 0 bottom
PC1232  47U_0805_6.3V6M  [C_0805]  74.51 135.96 180 bottom
PC1233  47U_0603_6.3V6M  [C_0603]  73.47 122.11 0 bottom
PC1234  47U_0603_6.3V6M  [C_0603]  77.85 132.78 0 bottom
PC1237  47U_0603_6.3V6M  [C_0603]  74.1 132.78 180 bottom
PC1246  47U_0603_6.3V6M  [C_0603]  77.22 123.32 180 bottom
PC1247  47U_0603_6.3V6M  [C_0603]  73.47 123.32 0 bottom
PC1248  47U_0805_6.3V6M  [C_0805]  74.51 134.24 180 bottom
PC1250  10U_0402_6.3V6M  [C_0402]  76.97 121.03 180 bottom
PC1251  47U_0603_6.3V6M  [C_0603]  77.22 122.11 180 bottom
PC1252  47U_0603_6.3V6M  [C_0603]  77.22 127.45 180 bottom
PC1253  47U_0603_6.3V6M  [C_0603]  103.38 129.29 270 top
PC1254  47U_0603_6.3V6M  [C_0603]  99.76 125.29 90 top
PC1255  47U_0603_6.3V6M  [C_0603]  102.17 129.29 270 top
PC1256  47U_0603_6.3V6M  [C_0603]  77.22 126.24 180 bottom
PC1258  47U_0603_6.3V6M  [C_0603]  100.97 129.29 270 bottom
PC1259  1U_0201_6.3V6M  [C_0201]  72.77 118.98 270 bottom
PC1260  1U_0201_6.3V6M  [C_0201]  78.26 130.94 0 bottom
PC1261  1U_0201_6.3V6M  [C_0201]  78.26 130.37 0 bottom
PC1262  1U_0201_6.3V6M  [C_0201]  78.26 129.22 0 bottom
PC1263  1U_0201_6.3V6M  [C_0201]  78.26 128.65 0 bottom
PC1265  1U_0201_6.3V6M  [C_0201]  78.26 129.8 0 bottom
PC1266  1U_0201_6.3V6M  [C_0201]  75.06 118.98 270 bottom
PC1267  1U_0201_6.3V6M  [C_0201]  75.63 118.98 270 bottom
PC1268  1U_0201_6.3V6M  [C_0201]  76.2 118.98 270 bottom
PC1269  1U_0201_6.3V6M  [C_0201]  74.76 121.22 0 bottom
PC1270  1U_0201_6.3V6M  [C_0201]  74.76 120.65 0 bottom
PC1272  1U_0201_6.3V6M  [C_0201]  74.47 118.96 270 bottom
PC1273  1U_0201_6.3V6M  [C_0201]  73.9 118.96 270 bottom
PC1274  1U_0201_6.3V6M  [C_0201]  73.33 118.96 270 bottom
PC1275  1U_0201_6.3V6M  [C_0201]  73.3 119.58 180 bottom
PC1276  1U_0201_6.3V6M  [C_0201]  86.55 130.27 90 bottom
PC1278  1U_0201_6.3V6M  [C_0201]  87.69 130.27 90 bottom
PC1279  47U_0603_6.3V6M  [C_0603]  103.38 129.29 270 bottom
PC1281  1U_0201_6.3V6M  [C_0201]  88.27 130.27 90 bottom
PC1282  1U_0201_6.3V6M  [C_0201]  84.77 119.36 270 bottom
PC1283  1U_0201_6.3V6M  [C_0201]  87.27 119.38 0 bottom
PC1284  1U_0201_6.3V6M  [C_0201]  87.27 118.81 0 bottom
PC1285  1U_0201_6.3V6M  [C_0201]  85.98 130.27 90 bottom
PC1287  1U_0201_6.3V6M  [C_0201]  85.94 118.81 0 bottom
PC1288  1U_0201_6.3V6M  [C_0201]  73.13 130.94 180 bottom
PC1289  1U_0201_6.3V6M  [C_0201]  73.13 130.37 180 bottom
PC1290  1U_0201_6.3V6M  [C_0201]  73.13 129.8 180 bottom
PC1291  1U_0201_6.3V6M  [C_0201]  71.35 127.76 180 bottom
PC1292  1U_0201_6.3V6M  [C_0201]  71.35 127.19 180 bottom
PC1293  1U_0201_6.3V6M  [C_0201]  71.35 126.62 180 bottom
PC1294  1U_0201_6.3V6M  [C_0201]  71.35 126.05 180 bottom
PC1295  1U_0201_6.3V6M  [C_0201]  71.35 128.34 180 bottom
PC1296  1U_0201_6.3V6M  [C_0201]  73.3 120.16 180 bottom
PC1297  1U_0201_6.3V6M  [C_0201]  72.06 122.04 180 bottom
PC1298  1U_0201_6.3V6M  [C_0201]  72.06 121.46 180 bottom
PC1299  1U_0201_6.3V6M  [C_0201]  72.06 120.89 180 bottom
PC1300  1U_0201_6.3V6M  [C_0201]  71.36 125.46 180 bottom
PC1301  1U_0201_6.3V6M  [C_0201]  71.36 124.89 180 bottom
PC1302  1U_0201_6.3V6M  [C_0201]  71.36 124.32 180 bottom
PC1303  1U_0201_6.3V6M  [C_0201]  71.36 123.75 180 bottom
PC1304  1U_0201_6.3V6M  [C_0201]  71.68 123.18 180 bottom
PC1305  1U_0201_6.3V6M  [C_0201]  71.68 122.61 180 bottom
PC1306  47U_0603_6.3V6M  [C_0603]  102.17 129.29 270 bottom
PC1309  1U_0201_6.3V6M  [C_0201]  85.41 130.27 90 bottom
PC1311  1U_0201_6.3V6M  [C_0201]  87.12 130.27 90 bottom
PC1312  47U_0805_6.3V6M  [C_0805]  90.74 122.85 90 bottom
PC1313  47U_0603_6.3V6M  [C_0603]  103.38 125.29 90 top
PC1314  47U_0805_6.3V6M  [C_0805]  94.3 122.87 90 bottom
PC1315  47U_0805_6.3V6M  [C_0805]  96.01 122.87 90 bottom
PC1316  47U_0805_6.3V6M  [C_0805]  94.3 127.41 270 bottom
PC1317  47U_0805_6.3V6M  [C_0805]  96.01 127.41 270 bottom
PC1318  47U_0603_6.3V6M  [C_0603]  102.17 125.29 90 top
PC1319  47U_0805_6.3V6M  [C_0805]  87.03 124.18 180 bottom
PC1320  47U_0805_6.3V6M  [C_0805]  90.36 128.94 90 bottom
PC1321  47U_0805_6.3V6M  [C_0805]  91.31 127.47 270 bottom
PC1322  47U_0603_6.3V6M  [C_0603]  68.9 127.7 180 bottom
PC1323  1U_0201_6.3V6M  [C_0201]  88.46 119.99 270 bottom
PC1324  47U_0805_6.3V6M  [C_0805]  94.23 128.94 90 bottom
PC1325  47U_0805_6.3V6M  [C_0805]  95.95 128.94 90 bottom
PC1326  47U_0603_6.3V6M  [C_0603]  83.32 134.51 0 bottom
PC1327  47U_0603_6.3V6M  [C_0603]  82.36 134.51 180 bottom
PC1328  47U_0603_6.3V6M  [C_0603]  82.08 122.72 0 bottom
PC1329  47U_0603_6.3V6M  [C_0603]  81.14 125.69 180 bottom
PC1330  47U_0603_6.3V6M  [C_0603]  82.11 125.69 0 bottom
PC1331  47U_0603_6.3V6M  [C_0603]  100.97 125.29 90 top
PC1335  47U_0603_6.3V6M  [C_0603]  99.76 125.29 90 bottom
PC1336  47U_0603_6.3V6M  [C_0603]  100.97 125.29 90 bottom
PC1337  47U_0603_6.3V6M  [C_0603]  102.17 125.29 90 bottom
PC1339  1U_0201_6.3V6M  [C_0201]  85.34 119.36 270 bottom
PC1340  1U_0201_6.3V6M  [C_0201]  85.94 119.38 0 bottom
PC1341  1U_0201_6.3V6M  [C_0201]  89.03 120.12 270 bottom
PC1355  1U_0201_6.3V6M  [C_0201]  67.86 131.07 180 bottom
PC1356  1U_0201_6.3V6M  [C_0201]  67.86 130.49 180 bottom
PC1357  47U_0805_6.3V6M  [C_0805]  69.3 124.97 180 bottom
PC1358  47U_0805_6.3V6M  [C_0805]  68.41 134.11 180 bottom
PC1359  47U_0805_6.3V6M  [C_0805]  68.87 121.48 0 bottom
PC1360  1U_0201_6.3V6M  [C_0201]  67.88 129.92 180 bottom
PC1361  47U_0603_6.3V6M  [C_0603]  68.45 135.57 180 bottom
PC1362  1U_0201_6.3V6M  [C_0201]  68.3 122.68 180 bottom
PC1363  47U_0603_6.3V6M  [C_0603]  70.29 135.38 0 bottom
PC1364  1U_0201_6.3V6M  [C_0201]  67.86 131.64 180 bottom
PC1365  1U_0201_6.3V6M  [C_0201]  68.3 123.83 180 bottom
PC1366  47U_0603_6.3V6M  [C_0603]  70.29 134.18 0 bottom
PC1368  47U_0603_6.3V6M  [C_0603]  68.45 132.59 180 bottom
PC1369  47U_0603_6.3V6M  [C_0603]  68.9 128.91 180 bottom
PC1370  1U_0201_6.3V6M  [C_0201]  68.3 123.26 180 bottom
PC1374  47U_0805_6.3V6M  [C_0805]  81.04 124.22 180 bottom
PC1375  47U_0805_6.3V6M  [C_0805]  82.18 124.22 0 bottom
PC1376  47U_0603_6.3V6M  [C_0603]  81.11 122.72 180 bottom
PC1377  47U_0603_6.3V6M  [C_0603]  81.6 132.77 180 bottom
PC1384  47U_0603_6.3V6M  [C_0603]  87.01 126.98 270 bottom
PC1385  47U_0603_6.3V6M  [C_0603]  85.8 126.98 270 bottom
PC1386  47U_0603_6.3V6M  [C_0603]  84.59 126.98 270 bottom
PC1387  47U_0603_6.3V6M  [C_0603]  87.01 121.45 90 bottom
PC1388  47U_0603_6.3V6M  [C_0603]  85.8 121.45 90 bottom
PC1389  47U_0603_6.3V6M  [C_0603]  103.38 125.29 90 bottom
PC1390  47U_0603_6.3V6M  [C_0603]  92.84 127.13 270 bottom
PC1391  47U_0603_6.3V6M  [C_0603]  92.77 129.16 90 bottom
PC1392  47U_0603_6.3V6M  [C_0603]  84.59 121.45 90 bottom
PC1393  47U_0603_6.3V6M  [C_0603]  99.76 129.29 270 bottom
PC1394  47U_0603_6.3V6M  [C_0603]  100.97 129.29 270 top
PC1395  47U_0603_6.3V6M  [C_0603]  99.76 129.29 270 top
PC1401  1U_0201_6.3V6M  [C_0201]  78.87 119.48 270 bottom
PC1402  1U_0201_6.3V6M  [C_0201]  79.44 119.48 270 bottom
PC1403  1U_0201_6.3V6M  [C_0201]  80.01 119.48 270 bottom
PC1404  1U_0201_6.3V6M  [C_0201]  83.02 118.94 0 bottom
PC1405  1U_0201_6.3V6M  [C_0201]  80.02 130.93 180 bottom
PC1406  1U_0201_6.3V6M  [C_0201]  82.45 128.61 0 bottom
PC1407  1U_0201_6.3V6M  [C_0201]  80.59 119.48 270 bottom
PC1408  1U_0201_6.3V6M  [C_0201]  81.17 119.48 270 bottom
PC1409  1U_0201_6.3V6M  [C_0201]  82.33 118.94 180 bottom
PC1410  1U_0201_6.3V6M  [C_0201]  82.33 119.51 180 bottom
PC1411  1U_0201_6.3V6M  [C_0201]  82.45 129.19 0 bottom
PC1412  1U_0201_6.3V6M  [C_0201]  82.45 129.76 0 bottom
PC1413  1U_0201_6.3V6M  [C_0201]  82.45 130.33 0 bottom
PC1414  1U_0201_6.3V6M  [C_0201]  82.45 130.9 0 bottom
PC1415  1U_0201_6.3V6M  [C_0201]  81.46 130.38 180 bottom
PC1416  1U_0201_6.3V6M  [C_0201]  80.02 130.37 180 bottom
PC1417  1U_0201_6.3V6M  [C_0201]  80.02 129.8 180 bottom
PC1418  1U_0201_6.3V6M  [C_0201]  80.02 129.22 180 bottom
PC1419  1U_0201_6.3V6M  [C_0201]  80.02 128.65 180 bottom
PC1420  1U_0201_6.3V6M  [C_0201]  81.46 129.8 180 bottom
PC1421  47U_0603_6.3V6M  [C_0603]  110.32 137.95 0 top
PC1422  47U_0603_6.3V6M  [C_0603]  110.35 139.37 0 top
PC1423  1U_0402_10V6K  [C_0402]  54.19 157.85 0 bottom
PC1424  82P_0402_50V8J  [C_0402]  93.65 158.46 270 bottom
PC1425  82P_0402_50V8J  [C_0402]  91.14 158.46 270 bottom
PC1426  82P_0402_50V8J  [C_0402]  89.81 158.46 270 bottom
PC1427  82P_0402_50V8J  [C_0402]  87.34 158.46 270 bottom
PC1428  82P_0402_50V8J  [C_0402]  84.76 158.46 270 bottom
PC1429  82P_0402_50V8J  [C_0402]  80.98 158.46 270 bottom
PC1430  82P_0402_50V8J  [C_0402]  79.65 158.46 270 bottom
PC1431  82P_0402_50V8J  [C_0402]  74.66 158.46 270 bottom
PC1432  82P_0402_50V8J  [C_0402]  72.07 158.46 270 bottom
PC1433  82P_0402_50V8J  [C_0402]  69.53 158.46 270 bottom
PC1434  1000P_0402_50V7K  [C_0402]  50.93 158.89 180 bottom
PC1435  1000P_0402_50V7K  [C_0402]  66.54 163.68 0 top
PC1436  1000P_0402_50V7K  [C_0402]  83.35 163.67 0 top
PC1437  1000P_0402_50V7K  [C_0402]  61.68 158.7 270 top
PC1438  2200P_0402_50V7K  [C_0402]  48.37 163.43 0 top
PC1439  2200P_0402_50V7K  [C_0402]  48.4 160.05 0 top
PC1440  2200P_0402_50V7K  [C_0402]  48.51 160.02 0 bottom
PD103  -  [RB520SM-30T2R_EMD2-2]  14.73 44.39 180 top
PD104  -  [TVNST52302AB0_SOT523-3]  140.21 97.92 180 top
PD105  -  [TVNST52302AB0_SOT523-3]  140.34 102.62 180 top
PD106  -  [RB520SM-30T2R_EMD2-2]  14.73 45.79 180 top
PD110  -  [RB520SM-30T2R_EMD2-2]  29.49 45.66 0 top
PD111  -  [RB520SM-30T2R_EMD2-2]  33.02 40.11 90 top
PD280  -  [BAT54CW_SOT323-3]  147.19 121.16 180 top
PD300  -  [DB2J31400L_SOD323-2]  137.6 132.9 270 top
PD301  -  [DB2J31400L_SOD323-2]  135.57 133.03 180 top
PD302  -  [RB520SM-30T2R_EMD2-2]  153.95 122.4 270 top
PD303  -  [RB520SM-30T2R_EMD2-2]  155.27 122.4 270 top
PD400  -  [DFLS160-7_POWERDI123-2]  69.98 71 270 top
PD906  SMF4L22A SOD123FL-2  [SMF22A-SOD123FL-2-S]  118.95 98.22 0 bottom
PJP500  PAD-OPEN 4X4M  [JUMP_43X118]  119.13 105.01 270 top
PJP501  PAD-OPEN 4X4M  [JUMP_43X118]  45.38 162.24 180 bottom
PJP502  PAD-OPEN 4X4M  [JUMP_43X118]  120.25 137.09 180 bottom
PJP600  -  [JUMP_43X79]  109.6 104.5 270 top
PJP601  -  [JUMP_43X39]  86.49 107.38 270 top
PJP700  -  [JUMP_43X79]  129.71 147 180 bottom
PJP720  -  [JUMP_43X39]  135.71 146.75 180 top
PJP721  -  [JUMP_43X39]  107.04 89.42 180 top
PJP800  -  [JUMP_43X79]  117.77 131.13 180 top
PJP801  -  [JUMP_43X79]  44.24 145.86 180 bottom
PL100  HCB2012KF-121T50_0805  [TAI-T_HCB2012KF-121T50_2P]  13.06 39.4 0 top
PL101  HCB2012KF-121T50_0805  [TAI-T_HCB2012KF-121T50_2P]  13.08 27.24 0 top
PL102  HCB2012KF-121T50_0805  [TAI-T_HCB2012KF-121T50_2P]  138.81 109.94 90 top
PL103  HCB2012KF-121T50_0805  [TAI-T_HCB2012KF-121T50_2P]  140.61 109.94 90 top
PL301  2.2UH_MMD-10BZN2R2M-M1L_10A_20%  [MAG_MMD-10BZN2R2M-M1L_2P]  135.19 110.66 180 top
PL302  1UH_1277AS-H-1R0N-P2_3.3A_30%  [TOKO_1277AS-H-1R0N-P2_2P]  116.43 100.08 0 top
PL400  10UH_MLPS-5020-100M-E_1.5A_20%  [MAG_MLPS-5020-100M-E_2P]  75.77 74.61 180 top
PL500  HCB2012KF-121T50_0805  [TAI-T_HCB2012KF-121T50_2P]  123.1 121.21 180 top
PL501  1.5UH_MMD-05AHN1R5M-M1L_6.2A_20%  [MAG_MMD-05AHN1R5M-M1L_2P]  119.15 113.82 270 top
PL502  HCB2012KF-121T50_0805  [TAI-T_HCB2012KF-121T50_2P]  47.29 149.94 180 top
PL503  1.5UH_MMD-05AHN1R5M-M1L_6.2A_20%  [MAG_MMD-05AHN1R5M-M1L_2P]  45.19 157.84 90 top
PL504  HCB2012KF-121T50_0805  [TAI-T_HCB2012KF-121T50_2P]  123.53 147.93 180 top
PL505  1.5UH_MMD-05AHN1R5M-M1L_6.2A_20%  [MAG_MMD-05AHN1R5M-M1L_2P]  118.6 140.67 270 top
PL600  1UH_MHCI05015B-1R0M-R8A_6.5A_20%  [CHILI_MHCI05015B-1R0M-R8A_2P]  109.86 113.88 270 top
PL601  HCB2012KF-121T50_0805  [TAI-T_HCB2012KF-121T50_2P]  109.16 126 270 top
PL700  HCB2012KF-121T50_0805  [TAI-T_HCB2012KF-121T50_2P]  127.51 138.57 90 bottom
PL701  1UH_MHCI04012-1R0M-R8EQ_4.2A_20%  [CHILI_MHCI04012-1R0M-R8EQ_2P]  129.03 143.63 90 top
PL720  HCB1608KF-121T30_0603  [TAI-T_HCB1608KF-121T3_L0603_2P]  142.39 136.78 90 top
PL721  2.2UH_1239AS-H-2R2N-P2_1.3A_30%  [TOKO_1239AS-H-2R2N-P2_2P]  139.18 145.86 180 top
PL722  HCB1608KF-121T30_0603  [TAI-T_HCB1608KF-121T3_L0603_2P]  110.87 101.2 270 top
PL723  2.2UH_1239AS-H-2R2N-P2_1.3A_30%  [TOKO_1239AS-H-2R2N-P2_2P]  109.09 93.12 270 top
PL800  HCB1608KF-121T30_0603  [TAI-T_HCB1608KF-121T3_L0603_2P]  127.13 131.42 270 top
PL801  1UH_1277AS-H-1R0N-P2_3.3A_30%  [TOKO_1277AS-H-1R0N-P2_2P]  119.76 126.09 90 top
PL802  HCB1608KF-121T30_0603  [TAI-T_HCB1608KF-121T3_L0603_2P]  52.26 149.52 270 top
PL803  1UH_1277AS-H-1R0N-P2_3.3A_30%  [TOKO_1277AS-H-1R0N-P2_2P]  45.4 143.62 90 top
PL1000  HCB2012KF-121T50_0805  [TAI-T_HCB2012KF-121T50_2P]  99.81 160.36 180 bottom
PL1002  HCB2012KF-121T50_0805  [TAI-T_HCB2012KF-121T50_2P]  99.81 162.19 180 bottom
PL1100  0.15UH_MMD-10BD-R15MEM2L_35A_20%  [MAG_MMD-10BD-R15MEM2L_2P]  85.62 154.91 270 top
PL1101  0.15UH_MMD-10BD-R15MEM2L_35A_20%  [MAG_MMD-10BD-R15MEM2L_2P]  68.81 154.8 270 top
PL1102  0.15UH_MMD-10BD-R15MEM2L_35A_20%  [MAG_MMD-10BD-R15MEM2L_2P]  96.8 149.65 0 top
PL1103  0.47UH_MHCI06015-R47MR8A7R45_10.8A_20%  [CHILI_MHCI06015-R47MR8A7R45_2P]  58.9 151.93 270 top
PQ100  -  [AON7405_DFN8-5]  16.79 39.16 270 top
PQ101  -  [AON7405_DFN8-5]  24.94 35.16 90 top
PQ102  -  [AON7405_DFN8-5]  30.73 32.32 180 top
PQ103  -  [AON7405_DFN8-5]  33.4 33.21 0 top
PQ104  S TR AO7401 1P SC70-3  [SI1303DL-T1-E3_SOT323-3]  24.37 39.56 90 top
PQ106  -  [DMN65D8LW-7_SOT323-3]  14.1 32.58 90 top
PQ108  -  [DMN65D8LW-7_SOT323-3]  25.65 41.28 180 top
PQ109  -  [DMN66D0LDW-7_SOT363-6]  22.91 41.6 90 top
PQ110  -  [DMN65D8LW-7_SOT323-3]  29.97 24 0 top
PQ111  -  [DMN65D8LW-7_SOT323-3]  28 17.78 180 top
PQ112  -  [DMN65D8LW-7_SOT323-3]  38.23 27.3 0 top
PQ113  -  [AON7405_DFN8-5]  17.64 26.77 270 top
PQ114  -  [AON7405_DFN8-5]  24.89 29.72 180 top
PQ115  S TR AO7401 1P SC70-3  [SI1303DL-T1-E3_SOT323-3]  27.3 22.12 0 top
PQ118  -  [DMN65D8LW-7_SOT323-3]  12.57 18.35 90 top
PQ119  -  [DMN65D8LW-7_SOT323-3]  25.4 19.68 0 top
PQ120  -  [DMN66D0LDW-7_SOT363-6]  145.27 132.59 0 top
PQ121  -  [DMN66D0LDW-7_SOT363-6]  21.38 23.23 270 top
PQ122  -  [DMN66D0LDW-7_SOT363-6]  143.83 125.94 270 top
PQ123  S TR AO7401 1P SC70-3  [SI1303DL-T1-E3_SOT323-3]  19.63 44.95 270 top
PQ124  S TR AO7401 1P SC70-3  [SI1303DL-T1-E3_SOT323-3]  25.02 48.29 90 top
PQ125  -  [DMN66D0LDW-7_SOT363-6]  25.91 45.79 270 top
PQ126  -  [DMN65D8LW-7_SOT323-3]  18.12 44.82 270 top
PQ127  -  [DMN66D0LDW-7_SOT363-6]  141.92 129.34 90 top
PQ128  -  [DMN66D0LDW-7_SOT363-6]  141.92 131.88 90 top
PQ129  -  [DMN66D0LDW-7_SOT363-6]  145.1 131.4 270 top
PQ130  -  [DMN65D8LW-7_SOT323-3]  36.97 47.21 180 top
PQ131  -  [DMN65D8LW-7_SOT323-3]  34.19 48.33 270 top
PQ132  -  [DMN65D8LW-7_SOT323-3]  30.35 44.32 0 top
PQ133  S TR AO7401 1P SC70-3  [SI1303DL-T1-E3_SOT323-3]  13.11 35.22 270 top
PQ134  -  [DMN66D0LDW-7_SOT363-6]  19.54 34.31 90 top
PQ135  S TR AO7401 1P SC70-3  [SI1303DL-T1-E3_SOT323-3]  13.34 22.16 270 top
PQ136  -  [DMN66D0LDW-7_SOT363-6]  19.68 21.15 90 top
PQ138  S TR AO7401 1P SC70-3  [SI1303DL-T1-E3_SOT323-3]  35.14 29.4 270 top
PQ139  -  [DMN66D0LDW-7_SOT363-6]  36.38 25.2 90 top
PQ140  -  [DMN65D8LW-7_SOT323-3]  36.13 45.79 270 top
PQ141  -  [DMN65D8LW-7_SOT323-3]  18.1 31.05 90 top
PQ142  -  [DMN65D8LW-7_SOT323-3]  16.38 18.35 90 top
PQ280  -  [DMN65D8LW-7_SOT323-3]  150.24 121.16 180 top
PQ302  -  [AON6380_DFN5X6-8-5]  131.44 100.52 90 top
PQ304  -  [AON7405_DFN8-5]  140.69 116.18 180 top
PQ305  -  [AON6508_DFN8-5]  133.86 99.25 0 top
PQ306  -  [AON6508_DFN8-5]  129.16 122.12 180 top
PQ307  -  [AON6508_DFN8-5]  131.06 120.72 270 top
PQ308  -  [DMN65D8LW-7_SOT323-3]  152.74 125.28 180 top
PR100  499K_0402_1%  [R_0402]  14.53 37.96 270 top
PR101  330K_0201_1%  [R_0201]  21.59 39.56 90 top
PR102  100K_0402_1%  [R_0402]  33.91 17.85 0 top
PR103  499K_0402_1%  [R_0402]  26.69 36.72 90 top
PR104  499K_0402_1%  [R_0402]  29.72 34.61 180 top
PR105  499K_0402_1%  [R_0402]  37.72 32.45 90 top
PR106  49.9K_0402_1%  [R_0402]  12.55 33.82 270 top
PR107  330K_0201_1%  [R_0201]  21.59 40.76 180 top
PR108  330K_0402_1%  [R_0402]  34.54 23.94 270 top
PR109  49.9K_0402_1%  [R_0402]  25.72 39.17 90 top
PR110  49.9K_0402_1%  [R_0402]  35.48 27.5 0 top
PR111  499K_0402_1%  [R_0402]  31.88 45.33 90 bottom
PR112  49.9K_0402_1%  [R_0402]  32.21 25.08 180 top
PR113  499K_0402_1%  [R_0402]  38.94 42.17 180 top
PR114  0_0402_5%  [R0402_0OHM]  27.36 41.72 0 top
PR115  200K_0201_5%  [R_0201]  23.94 43.03 270 top
PR116  0_0603_5%  [R_0603]  38.1 36.13 180 top
PR117  0_0402_5%  [R_0402]  31.18 46.72 90 top
PR118  330K_0201_1%  [R_0201]  23.11 24.07 180 top
PR119  1M_0402_1%  [R_0402]  34.54 22.16 180 top
PR120  0_0402_5%  [R_0402]  38.1 45.01 90 top
PR121  0_0402_5%  [R_0402]  28.91 20.89 180 top
PR122  0_0402_5%  [R_0402]  20.57 33.72 270 top
PR123  0_0402_5%  [R0402_0OHM]  19.11 43.02 0 top
PR124  200K_0201_5%  [R_0201]  138.94 130.51 270 top
PR125  0_0402_5%  [R0402_0OHM]  38.73 48.53 90 top
PR126  1M_0402_1%  [R_0402]  138.94 111.11 90 bottom
PR127  200K_0201_5%  [R_0201]  144.64 135.51 0 top
PR128  499K_0402_1%  [R_0402]  15.24 25.59 270 top
PR129  330K_0201_1%  [R_0201]  23.75 24.7 270 top
PR130  499K_0402_1%  [R_0402]  25.4 24.4 270 top
PR132  0_0402_5%  [R_0402]  17.53 20.13 0 top
PR133  49.9K_0402_1%  [R_0402]  14.48 20.26 180 top
PR134  49.9K_0402_1%  [R_0402]  24.56 22.54 0 top
PR135  0_0402_5%  [R0402_0OHM]  23.62 19.48 90 top
PR136  0_0402_5%  [R0402_0OHM]  21.64 20.89 0 top
PR137  0_0402_5%  [R_0402]  32.38 23.1 90 top
PR138  0_0402_5%  [R0402_0OHM]  143 130.82 270 top
PR139  200K_0201_5%  [R_0201]  20.57 21.15 90 top
PR142  200K_0201_5%  [R_0201]  142.11 128.09 270 bottom
PR143  200K_0201_5%  [R_0201]  145.66 133.55 0 bottom
PR144  0_0402_5%  [R0402_0OHM]  144.02 130.67 90 top
PR145  0_0402_5%  [R0402_0OHM]  144.02 132.58 90 top
PR146  0_0402_5%  [R0402_0OHM]  31.18 48.5 90 top
PR147  0_0805_5%  [R_0805]  20.71 48.73 270 top
PR148  1M_0201_1%  [R_0201]  22.63 43.97 90 top
PR149  300K_0402_5%  [R_0402]  19.3 49.62 270 bottom
PR150  10K_0402_1%  [R_0402]  24 44.52 0 top
PR151  0_0201_5%  [R_0201]  27.94 42.83 90 top
PR152  100_0402_1%  [R_0402]  140.84 101.36 270 top
PR153  300K_0402_5%  [R_0402]  20.19 49.6 0 bottom
PR154  100_0402_1%  [R_0402]  139.7 101.36 270 top
PR155  100K_0201_1%  [R_0201]  28.7 44.64 270 top
PR156  0_0201_5%  [R_0201]  28.7 45.28 90 top
PR157  0_0402_5%  [R_0402]  139.94 105.03 0 top
PR158  200K_0201_5%  [R_0201]  29.84 18.65 270 top
PR160  200K_0201_5%  [R_0201]  29.72 17.46 180 top
PR161  0_0402_5%  [R_0402]  29.84 20.33 270 top
PR162  390K_0402_1%  [R_0402]  27.13 20.89 180 top
PR163  1M_0402_1%  [R_0402]  32.77 48.27 270 bottom
PR164  1M_0402_1%  [R_0402]  37.21 45.92 270 top
PR165  0_0402_5%  [R_0402]  29.51 41.21 0 top
PR166  1M_0201_1%  [R_0201]  17.03 32.55 90 top
PR167  0_0402_5%  [R_0402]  35.26 47.56 90 top
PR172  1M_0201_1%  [R_0201]  15.44 17.97 270 top
PR174  200K_0201_5%  [R_0201]  142.11 128.34 0 top
PR175  200K_0201_5%  [R_0201]  147.96 129.47 90 bottom
PR176  1M_0201_1%  [R_0201]  19.93 42.13 180 top
PR177  1M_0201_1%  [R_0201]  24.55 21.4 0 top
PR178  1M_0201_1%  [R_0201]  27.85 40.96 180 top
PR179  1M_0201_1%  [R_0201]  23.62 18.06 90 top
PR182  47K_0402_1%  [R_0402]  32.13 46.55 270 top
PR183  221K_0402_1%  [R_0402]  30.1 47.36 90 bottom
PR184  47K_0402_1%  [R_0402]  33.02 43.83 270 top
PR185  221K_0402_1%  [R_0402]  36.31 40.71 0 top
PR192  0_0402_5%  [R_0402]  144.02 129.81 270 top
PR200  0_0402_5%  [R_0402]  141.74 124.54 0 top
PR201  0_0402_5%  [R0402_0OHM]  143 132.73 270 top
PR202  0_0402_5%  [R_0402]  140.96 132.21 0 bottom
PR203  0_0402_5%  [R_0402]  141.86 129.78 90 bottom
PR204  0_0402_5%  [R_0402]  145.66 132.59 0 bottom
PR206  0_0402_5%  [R_0402]  145.78 124.84 0 bottom
PR207  0_0402_5%  [R_0402]  148.27 131.46 270 top
PR208  0_0402_5%  [R_0402]  146.7 130.3 180 bottom
PR209  0_0402_5%  [R_0402]  140.6 128.08 180 top
PR213  330K_0201_1%  [R_0201]  15.93 35.7 270 top
PR214  330K_0201_1%  [R_0201]  16.03 34.25 0 top
PR215  200K_0201_5%  [R_0201]  20.45 34.53 90 top
PR216  0_0402_5%  [R_0402]  37.97 46.8 0 top
PR217  0_0402_5%  [R0402_0OHM]  19.7 32.96 180 top
PR218  1M_0402_1%  [R_0402]  15.11 45.48 270 bottom
PR219  1M_0402_1%  [R_0402]  19.56 28.25 90 top
PR220  330K_0201_1%  [R_0201]  16.13 22.29 270 top
PR221  330K_0201_1%  [R_0201]  16.26 21.02 0 top
PR222  200K_0201_5%  [R_0201]  20.57 22.42 90 top
PR224  0_0402_5%  [R0402_0OHM]  15.71 20.16 0 top
PR225  0_0402_5%  [R_0402]  33.07 46.53 270 top
PR228  1M_0201_1%  [R_0201]  16.62 35.12 90 top
PR229  1M_0201_1%  [R_0201]  16.89 21.74 90 top
PR230  0_0402_5%  [R_0402]  145.78 131.45 0 bottom
PR231  0_0805_5%  [R_0805]  22.91 45.89 0 top
PR248  49.9K_0402_1%  [R_0402]  35.81 22.16 0 top
PR249  100K_0402_1%  [R_0402]  30.73 19.37 90 top
PR250  330K_0201_1%  [R_0201]  38.48 28.93 270 top
PR251  330K_0201_1%  [R_0201]  37.85 29.57 270 top
PR252  200K_0201_5%  [R_0201]  32.98 25.08 0 top
PR253  0_0402_5%  [R_0402]  33.4 23.05 90 top
PR255  200K_0402_1%  [R_0402]  30.99 48.27 270 bottom
PR256  200K_0402_1%  [R_0402]  30.99 46.24 270 bottom
PR257  200K_0402_1%  [R_0402]  37.22 39.82 180 top
PR258  200K_0402_1%  [R_0402]  38.02 43.05 0 top
PR259  200K_0201_5%  [R_0201]  17.83 33.12 270 top
PR261  0_0402_5%  [R_0402]  21.36 31.54 270 top
PR262  200K_0201_5%  [R_0201]  21.34 32.32 90 top
PR263  200K_0201_5%  [R_0201]  15.44 19.24 270 top
PR264  200K_0201_5%  [R_0201]  19.81 20 180 top
PR265  0_0402_5%  [R_0402]  19.43 18.73 270 top
PR266  0_0402_5%  [R_0402]  35.43 23.05 90 top
PR267  100K_0402_1%  [R_0402]  32 17.85 0 top
PR268  0_0603_5%  [R_0603]  27.18 31.82 270 top
PR269  1M_0201_1%  [R_0201]  30.33 48.82 90 top
PR270  1M_0201_1%  [R_0201]  38.84 45.66 270 top
PR271  0_0201_5%  [R_0201]  16.51 43.12 0 top
PR272  1M_0201_1%  [R_0201]  30.77 21.15 180 top
